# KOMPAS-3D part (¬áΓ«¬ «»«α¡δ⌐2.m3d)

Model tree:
1. Эскиз:11
2. Операция выдавливания:8
     Расстояние 1 = 1.5; Расстояние 2 = 2
3. Эскиз:19
4. Операция выдавливания:11
     Расстояние 1 = 12; Расстояние 2 = 2
5. Эскиз:20
6. Смещенная плоскость:1
     Расстояние = 2.5
7. Эскиз:43
8. Операция выдавливания:19
     Расстояние 1 = 10
9. Вырезать элемент выдавливания:23
     Расстояние 2 = 0.5; Расстояние 1 = 5.5
10. Эскиз:44
11. Вырезать элемент выдавливания:24
     Расстояние 2 = 0.5; Расстояние 1 = 0.5
12. Эскиз:45
13. Вырезать элемент выдавливания:25
     Расстояние 2 = 0.5; Расстояние 1 = 0.5
14. Эскиз:46
15. Операция выдавливания:20
     Расстояние 1 = 3.5
16. Эскиз:47
17. Вырезать элемент выдавливания:26
     Расстояние 2 = 0.5; Расстояние 1 = 5.5
18. Эскиз:48
19. Вырезать элемент выдавливания:27
     Расстояние 2 = 0.5; Расстояние 1 = 5
20. Скругление:14
     Радиус = 0.5
21. Скругление:15
     Радиус = 0.1
22. Скругление:16
     Радиус = 0.1
23. Фаска:3
     Угол = 45; Длина 1 = 0.5; Длина 2 = 0.5
24. Эскиз:49
25. Вырезать элемент выдавливания:28
     Расстояние 2 = 0.5; Расстояние 1 = 2
26. Скругление:17
     Радиус = 1
27. Скругление:18
     Радиус = 1
28. Эскиз:50
29. Операция выдавливания:21
     Расстояние 1 = 1
30. Эскиз:51
31. Операция выдавливания:22
     Расстояние 1 = 0.5
32. Скругление:19
     Радиус = 0.1
33. Скругление:20
     Радиус = 0.1
34. Массив по концентрической сетке:5  (with: Вырезать элемент выдавливания:28, Скругление:17, Скругление:18, Операция выдавливания:21, Операция выдавливания:22, Скругление:19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)  (labels: Экземпляр ( 1, 1 ); Экземпляр ( 1, 2 ); Экземпляр ( 1, 3 ); Экземпляр ( 1, 4 ))
     N 2 = 6; Шаг 2 = 360; Номер 2 = 1
35. Эскиз:52
36. Вырезать элемент выдавливания:29
     Расстояние 1 = 2

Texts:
  Сплав АЛ8  ГОСТ 1583-93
